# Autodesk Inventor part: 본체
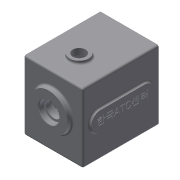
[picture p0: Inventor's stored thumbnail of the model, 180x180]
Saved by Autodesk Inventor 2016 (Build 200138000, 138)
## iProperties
Created: 2016-02
Part Number: 본체
Material: 알루미늄 6061
Document SubType Name: Modeling
Designer: mduedu
Density: 2.7 g/cm^3
Appearance: 기본값
Mass: 1510.33 g
Surface Area: 1077.08 cm^2
Volume: 559.381 cm^3
Author: mduedu
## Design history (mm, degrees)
sketch "스케치1"
  geometry: L1 (-47, -47)-(47, -47); L2 (47, -47)-(47, 63); L3 (47, 63)-(-47, 63); L4 (-47, 63)-(-47, -47); 2 further points
  constraints: 8 end point, 2 parallel, 1 horizontal, 1 midpoint, 1 perpendicular, 1 vertical alignment
  dimensions: "d0" = 94 distance of L2.end L3.end; "d155" = 110 distance of L1.end L2.end; "d156" = 47 distance from line of L1 point (0, 0)
extrude "돌출1" new body sketch "스케치1" distance "d2" = 120; taper "d3" = 0 deg
sketch "스케치3"
  geometry: L1 (47, -47)-(-47, -47) reference; L2 (47, 63)-(47, -47) reference; L3 (-47, 63)-(47, 63) reference; L4 (-47, -47)-(-47, 63) reference; L5 (37, 53)-(37, -37); L6 (37, -37)-(-37, -37); L7 (-37, -37)-(-37, 53); L8 (-37, 53)-(37, 53); 1 further point
  constraints: 8 end point, 3 other
  dimensions: "d226" = 10 distance between parallel lines of L8 L3
extrude "돌출3" cut sketch "스케치3" distance "d11" = 110; taper "d12" = 0 deg
sketch "스케치4"
  geometry: C1 r 21 at (0, 11); 1 further point
  constraints: 1 centre point, 1 vertical alignment
  dimensions: "d13" = 21 radius of C1; "d227" = 11 distance of point (0, 0) C1.centre
extrude "돌출4" join sketch "스케치4" distance "d16" = 7; taper "d17" = 0 deg
sketch "스케치5"
  geometry: C1 r 15 at (0, -20); 1 further point
  constraints: 1 centre point, 1 vertical alignment
  dimensions: "d18" = 15 radius of C1; "d20" = 20 distance of point (0, 0) C1.centre
extrude "돌출5" join sketch "스케치5" distance "d21" = 7; taper "d22" = 0 deg
sketch "스케치6"
  geometry: C1 r 30 at (0, 11); A1 r 21 centre (0, 11) between (8.978, -7.984) and (-8.978, -7.984) reference; 1 further point
  constraints: 1 centre point, 1 coincident
  dimensions: "d228" = 60 diameter of C1
extrude "돌출6" join sketch "스케치6" distance "d25" = 7; taper "d26" = -3 deg
hole "구멍1" diameter "d29" = 35; stored, may be unused: countersink angle "d33" = 90 deg, drill point angle "d35" = 0 deg; dims "d27" = 10, "d28" = 10, "d30" = 6, "d31" = 4, "d32" = 2, "d34" = 10
hole "구멍2" diameter "d38" = 22; stored, may be unused: countersink angle "d42" = 90 deg, drill point angle "d44" = 0 deg; dims "d36" = 10, "d37" = 10, "d39" = 6, "d40" = 4, "d41" = 2, "d43" = 7
hole "구멍3" diameter "d47" = 19; stored, may be unused: countersink angle "d51" = 90 deg, drill point angle "d53" = 0 deg; dims "d45" = 10, "d46" = 10, "d48" = 6, "d49" = 4, "d50" = 2, "d52" = 1
hole "구멍4" diameter "d56" = 32; stored, may be unused: countersink angle "d60" = 90 deg, drill point angle "d62" = 0 deg; dims "d57" = 6, "d58" = 4, "d59" = 2, "d61" = 8, "d220" = 10, "d221" = 10
hole "구멍5" diameter "d65" = 25; stored, may be unused: countersink angle "d69" = 90 deg, drill point angle "d71" = 0 deg; dims "d63" = 10, "d64" = 10, "d66" = 6, "d67" = 4, "d68" = 2, "d70" = 8
fillet "모깎기2" dims "d73" = 0.3
fillet "모깎기3" dims "d74" = 2
chamfer "모따기1" distance "d75" = 1; stored, may be unused: second distance "d76" = 2, angle "d77" = 45 deg
fillet "모깎기4" dims "d78" = 3
fillet "모깎기23" dims "d240" = 1
fillet "모깎기20" dims "d229" = 3
sketch "스케치23"
  geometry: L1 (-37, 53)-(37, 53) reference; L2 (37, 53)-(37, -37) reference; L3 (37, -37)-(-37, -37) reference; L4 (-37, -37)-(-37, 53) reference; L5 (44, -47)-(-44, -47) reference; L6 (47, 60)-(47, -44) reference; L7 (-44, 63)-(44, 63) reference; L8 (-47, -44)-(-47, 60) reference; C1 r 10 at (-37, 53); C2 r 10 at (37, 53); C3 r 10 at (-37, -37); C4 r 10 at (37, -37); A1 r 3 centre (-44, -44) between (-47, -44) and (-44, -47) reference; A2 r 3 centre (44, -44) between (44, -47) and (47, -44) reference; A3 r 3 centre (44, 60) between (47, 60) and (44, 63) reference; A4 r 3 centre (-44, 60) between (-44, 63) and (-47, 60) reference; 1 further point
  constraints: 4 centre point, 4 coincident, 3 equal radius
  dimensions: "d230" = 20 diameter of C1
extrude "돌출22" join sketch "스케치23" stored distance "d235" = 10; taper "d236" = 0 deg
fillet "모깎기21" dims "d237" = 3
node "작업 평면1"
fillet "모깎기22" dims "d239" = 1
sketch "스케치12"
  geometry: A1 r 10 centre (-37, 53) between (-34.692, 43.27) and (-27.27, 50.692) reference; A2 r 10 centre (37, 53) between (27.27, 50.692) and (34.692, 43.27) reference; A3 r 10 centre (37, -37) between (34.692, -27.27) and (27.27, -34.692) reference; A4 r 10 centre (-37, -37) between (-27.27, -34.692) and (-34.692, -27.27) reference; 5 further points
  constraints: 4 coincident
hole "구멍6" sketch "스케치12" at (-37, 53), (37, 53), (37, -37), (-37, -37) diameter "d122" = 3.242; stored, may be unused: countersink angle "d126" = 90 deg, drill point angle "d128" = 120 deg; dims "d123" = 7, "d124" = 4, "d125" = 2, "d127" = 9
sketch "스케치20"
  geometry: L1 (44, 0)-(-44, 0) reference; L2 (44, -120)-(-44, -120) reference; L3 (0, 0)-(0, -120); L4 (-44, -120)-(-44, 0) reference; L5 (44, 0)-(44, -120) reference; C1 r 10 at (0, -79)
  constraints: 2 end point, 1 centre point, 1 midpoint, 1 point on line
  dimensions: "d189" = 20 diameter of C1; "d190" = 41 distance from line of C1.centre L2
extrude "돌출19" cut sketch "스케치20" stored distance "d191" = 10; taper "d192" = 0 deg
sketch "스케치18"
  geometry: C1 r 15 at (0, -79); C2 r 10 at (0, -79) reference; 1 further point
  constraints: 1 centre point, 1 concentric
  dimensions: "d174" = 30 diameter of C1
extrude "돌출17" join sketch "스케치18" distance "d175" = 5; taper "d176" = 0 deg
fillet "모깎기16" dims "d177" = 3
sketch "스케치19"
  geometry: C1 r 15 at (24.351, 79); C2 r 10 at (24.351, 79) reference; 1 further point
  constraints: 1 centre point, 1 concentric
  dimensions: "d178" = 30 diameter of C1
extrude "돌출18" cut sketch "스케치19" distance "d181" = 5; taper "d182" = 0 deg
chamfer "모따기5" distance "d183" = 1; stored, may be unused: second distance "d184" = 2, angle "d185" = 45 deg
fillet "모깎기24" dims "d242" = 3, "d243" = 3
sketch "스케치24"
  geometry: L1 (-95, 67)-(-25, 67); L2 (-25, 67)-(-25, 37); L3 (-25, 37)-(-95, 37); L4 (-95, 37)-(-95, 67); L5 (0, 0)-(0, 104) reference; L6 (-95, 52)-(-25, 52); L7 (-60, 67)-(-60, 37); A1 r 15 centre (-95, 52) between (-95, 37) and (-95, 67); A2 r 15 centre (-25, 52) between (-25, 67) and (-25, 37); A3 r 15 centre (-25, 52) between (-25, 37) and (-25, 67); A4 r 15 centre (-95, 52) between (-95, 67) and (-95, 37); 2 further points
  constraints: 12 end point, 8 point on circle, 5 midpoint, 4 centre point, 2 parallel, 2 perpendicular, 1 horizontal, 1 horizontal alignment
  dimensions: "d244" = 60 distance between parallel lines of L7 L5; "d245" = 100 dimension on A2 A1; "d246" = 30 distance between parallel lines of L3 L1
extrude "돌출23" join sketch "스케치24" distance "d247" = 3; taper "d248" = 0 deg
fillet "모깎기25" dims "d249" = 3
sketch "스케치25"
  geometry: L1 (-25, 67)-(-95, 67) reference; L2 (-95, 37)-(-25, 37) reference; A1 r 15 centre (-95, 52) between (-95, 67) and (-95, 37) reference; A2 r 15 centre (-25, 52) between (-25, 37) and (-25, 67) reference; 3 further points
  constraints: 1 horizontal alignment, 1 midpoint, 1 vertical alignment, 1 other
feature "엠보싱3" sketch "스케치25" dims "d250" = 0.5, "d251" = 0
sketch "스케치26"
  geometry: L1 (14.367, 127)-(73.633, 127) reference; L2 (0, 0)-(88, 0) reference; L3 (88, 120)-(0, 120) reference; 5 further points
  constraints: 3 vertical alignment, 2 midpoint
  dimensions: "d252" = 35 distance from line of point (44, 35) L2; "d253" = 35 distance from line of point (44, 85) L3; "d254" = 50 distance of point (44, 35) point (44, 85) (derived)
hole "구멍8" sketch "스케치26" at (44, 85), (44, 35) diameter "d255" = 6.647; stored, may be unused: countersink angle "d259" = 90 deg, drill point angle "d261" = 118 deg; dims "d256" = 6, "d257" = 4, "d258" = 2, "d260" = 8
node "솔리드1"
node "투영된 루프1"
node "투영된 루프4"
node "투영된 루프5"
node "투영된 루프6"
